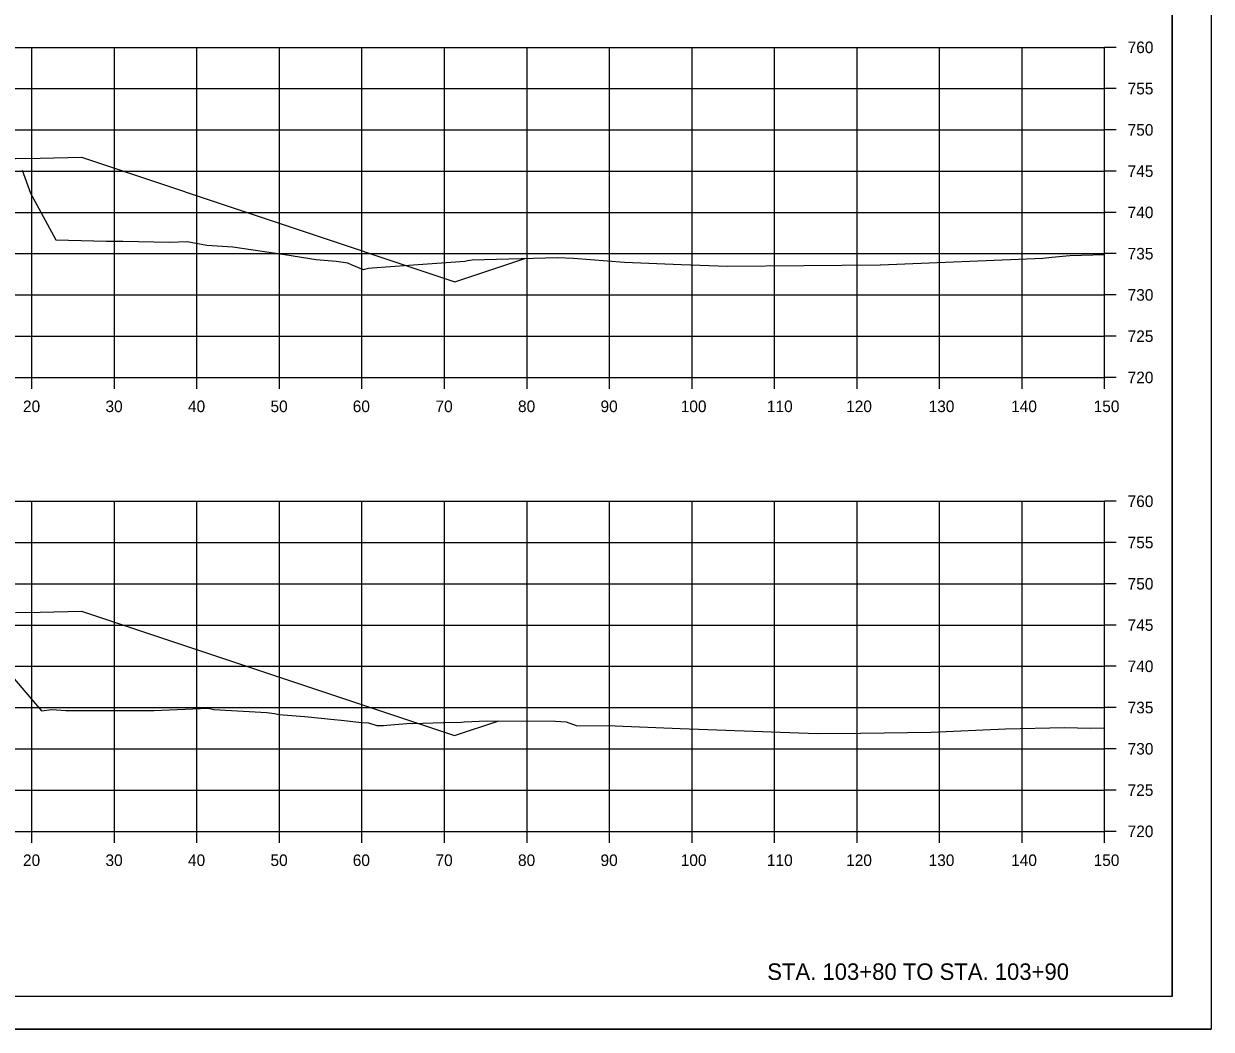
# Model space of a CAD drawing. Extents: x 1202951 to 1376887, y 378065 to 728038.
# Drawn here: x 1374304 to 1374447.9, y 379826.6 to 379948.5 of the extents above; entities that cross this region are included whole.
import ezdxf

# ---------------------------------------------------------------- set-up
doc = ezdxf.new("R2010")
doc.units = 0
for name, color, linetype in [('R_Axis', 7, 'Continuous'), ('R_Axis Annot', 7, 'Continuous'), ('R_Draft', 7, 'Continuous'), ('R_Exist Surface', 7, 'Continuous'), ('R_Fin Surface', 7, 'Continuous'), ('R_Grid', 7, 'Continuous'), ('R_No Plot', 7, 'Continuous')]:
    doc.layers.add(name, color=color, linetype=linetype)

msp = doc.modelspace()

# ---------------------------------------------------------------- linework, layer by layer
at = {"layer": 'R_Axis'}
for p, q in [((1374434.98, 379905.61), (1374434.98, 379945.61)), ((1374436.38, 379945.61), (1374434.98, 379945.61)), ((1374436.38, 379940.61), (1374434.98, 379940.61)), ((1374436.38, 379935.61), (1374434.98, 379935.61)), ((1374436.38, 379930.61), (1374434.98, 379930.61)), ((1374436.38, 379925.61), (1374434.98, 379925.61)), ((1374436.38, 379920.61), (1374434.98, 379920.61)), ((1374436.38, 379915.61), (1374434.98, 379915.61)), ((1374436.38, 379910.61), (1374434.98, 379910.61)), ((1374134.98, 379905.61), (1374434.98, 379905.61)), ((1374304.98, 379904.21), (1374304.98, 379905.61)), ((1374314.98, 379904.21), (1374314.98, 379905.61)), ((1374324.98, 379904.21), (1374324.98, 379905.61)), ((1374334.98, 379904.21), (1374334.98, 379905.61)), ((1374344.98, 379904.21), (1374344.98, 379905.61)), ((1374354.98, 379904.21), (1374354.98, 379905.61)), ((1374364.98, 379904.21), (1374364.98, 379905.61)), ((1374374.98, 379904.21), (1374374.98, 379905.61)), ((1374384.98, 379904.21), (1374384.98, 379905.61)), ((1374394.98, 379904.21), (1374394.98, 379905.61)), ((1374404.98, 379904.21), (1374404.98, 379905.61)), ((1374414.98, 379904.21), (1374414.98, 379905.61)), ((1374424.98, 379904.21), (1374424.98, 379905.61)), ((1374434.98, 379904.21), (1374434.98, 379905.61)), ((1374436.38, 379905.61), (1374434.98, 379905.61)), ((1374434.98, 379850.61), (1374434.98, 379890.61)), ((1374436.38, 379890.61), (1374434.98, 379890.61)), ((1374436.38, 379885.61), (1374434.98, 379885.61)), ((1374436.38, 379880.61), (1374434.98, 379880.61)), ((1374436.38, 379875.61), (1374434.98, 379875.61)), ((1374436.38, 379870.61), (1374434.98, 379870.61)), ((1374436.38, 379865.61), (1374434.98, 379865.61)), ((1374436.38, 379860.61), (1374434.98, 379860.61)), ((1374436.38, 379855.61), (1374434.98, 379855.61)), ((1374134.98, 379850.61), (1374434.98, 379850.61)), ((1374304.98, 379849.21), (1374304.98, 379850.61)), ((1374314.98, 379849.21), (1374314.98, 379850.61)), ((1374324.98, 379849.21), (1374324.98, 379850.61)), ((1374334.98, 379849.21), (1374334.98, 379850.61)), ((1374344.98, 379849.21), (1374344.98, 379850.61)), ((1374354.98, 379849.21), (1374354.98, 379850.61)), ((1374364.98, 379849.21), (1374364.98, 379850.61)), ((1374374.98, 379849.21), (1374374.98, 379850.61)), ((1374384.98, 379849.21), (1374384.98, 379850.61)), ((1374394.98, 379849.21), (1374394.98, 379850.61)), ((1374404.98, 379849.21), (1374404.98, 379850.61)), ((1374414.98, 379849.21), (1374414.98, 379850.61)), ((1374424.98, 379849.21), (1374424.98, 379850.61)), ((1374434.98, 379849.21), (1374434.98, 379850.61)), ((1374436.38, 379850.61), (1374434.98, 379850.61))]:
    msp.add_line(p, q, dxfattribs=at)
at = {"layer": 'R_Exist Surface'}
for points in [[(1374303.79, 379930.74), (1374304.79, 379927.92), (1374307.86, 379922.27), (1374314.03, 379922.13), (1374316, 379922.12), (1374321.64, 379922), (1374323.8, 379922.09), (1374326.19, 379921.63), (1374329.31, 379921.44), (1374335.62, 379920.52), (1374339.41, 379919.91), (1374341.87, 379919.7), (1374343, 379919.53), (1374343.23, 379919.51), (1374343.75, 379919.25), (1374345.13, 379918.7), (1374345.77, 379918.84), (1374346.2, 379918.88), (1374350.66, 379919.2), (1374357.46, 379919.7), (1374357.76, 379919.78), (1374358.35, 379919.88), (1374368.71, 379920.13), (1374370.63, 379920.08), (1374376.78, 379919.58), (1374383.67, 379919.3), (1374389.29, 379919.1), (1374407.77, 379919.24), (1374407.82, 379919.24), (1374407.83, 379919.24), (1374427.48, 379920.08), (1374428.61, 379920.19), (1374430.77, 379920.4), (1374434.98, 379920.51)], [(1374302.6, 379869.38), (1374306.13, 379865.23), (1374307.38, 379865.37), (1374309.1, 379865.26), (1374319.61, 379865.24), (1374319.65, 379865.24), (1374319.79, 379865.25), (1374326.32, 379865.52), (1374327.01, 379865.39), (1374333.45, 379865), (1374334.37, 379864.87), (1374334.92, 379864.78), (1374338.05, 379864.51), (1374341.61, 379864.17), (1374342.44, 379864.07), (1374344.95, 379863.79), (1374345.78, 379863.76), (1374346.77, 379863.44), (1374347.58, 379863.45), (1374347.99, 379863.49), (1374350.91, 379863.7), (1374351.09, 379863.67), (1374354.86, 379863.79), (1374357.04, 379863.83), (1374357.36, 379863.86), (1374360.1, 379864.02), (1374368.45, 379863.96), (1374369.73, 379863.86), (1374370.92, 379863.45), (1374375.66, 379863.38), (1374383.56, 379863.06), (1374400.14, 379862.47), (1374405.41, 379862.51), (1374413.98, 379862.61), (1374422.97, 379863.04), (1374430.14, 379863.18), (1374433.28, 379863.13), (1374434.98, 379863.16)]]:
    msp.add_lwpolyline(points, dxfattribs=at)
at = {"layer": 'R_Fin Surface'}
for points in [[(1374193.18, 379923.57), (1374196.24, 379922.56), (1374208.04, 379918.62), (1374209.01, 379919.28), (1374216.4, 379921.41), (1374229.62, 379925.81), (1374247.4, 379931.74), (1374248.44, 379932.09), (1374253.44, 379931.99), (1374256.44, 379931.93), (1374256.93, 379931.93), (1374256.94, 379931.43), (1374257.94, 379931.45), (1374284.98, 379931.99), (1374301.48, 379931.66), (1374302.48, 379931.64), (1374302.49, 379932.14), (1374302.98, 379932.14), (1374305.98, 379932.2), (1374310.98, 379932.3), (1374312.56, 379931.77), (1374356.23, 379917.21), (1374364.7, 379920.03)], [(1374302.98, 379877.12), (1374305.98, 379877.18), (1374310.98, 379877.28), (1374312.32, 379876.84), (1374356.19, 379862.21), (1374361.57, 379864.01)]]:
    msp.add_lwpolyline(points, dxfattribs=at)
at = {"layer": 'R_Grid'}
for p, q in [((1374134.98, 379945.61), (1374434.98, 379945.61)), ((1374304.98, 379905.61), (1374304.98, 379945.61)), ((1374314.98, 379905.61), (1374314.98, 379945.61)), ((1374324.98, 379905.61), (1374324.98, 379945.61)), ((1374334.98, 379905.61), (1374334.98, 379945.61)), ((1374344.98, 379905.61), (1374344.98, 379945.61)), ((1374354.98, 379905.61), (1374354.98, 379945.61)), ((1374364.98, 379905.61), (1374364.98, 379945.61)), ((1374374.98, 379905.61), (1374374.98, 379945.61)), ((1374384.98, 379905.61), (1374384.98, 379945.61)), ((1374394.98, 379905.61), (1374394.98, 379945.61)), ((1374404.98, 379905.61), (1374404.98, 379945.61)), ((1374414.98, 379905.61), (1374414.98, 379945.61)), ((1374424.98, 379905.61), (1374424.98, 379945.61)), ((1374434.98, 379905.61), (1374434.98, 379945.61)), ((1374134.98, 379940.61), (1374434.98, 379940.61)), ((1374134.98, 379935.61), (1374434.98, 379935.61)), ((1374134.98, 379930.61), (1374434.98, 379930.61)), ((1374134.98, 379925.61), (1374434.98, 379925.61)), ((1374134.98, 379920.61), (1374434.98, 379920.61)), ((1374134.98, 379915.61), (1374434.98, 379915.61)), ((1374134.98, 379910.61), (1374434.98, 379910.61)), ((1374134.98, 379905.61), (1374434.98, 379905.61)), ((1374134.98, 379890.61), (1374434.98, 379890.61)), ((1374304.98, 379850.61), (1374304.98, 379890.61)), ((1374314.98, 379850.61), (1374314.98, 379890.61)), ((1374324.98, 379850.61), (1374324.98, 379890.61)), ((1374334.98, 379850.61), (1374334.98, 379890.61)), ((1374344.98, 379850.61), (1374344.98, 379890.61)), ((1374354.98, 379850.61), (1374354.98, 379890.61)), ((1374364.98, 379850.61), (1374364.98, 379890.61)), ((1374374.98, 379850.61), (1374374.98, 379890.61)), ((1374384.98, 379850.61), (1374384.98, 379890.61)), ((1374394.98, 379850.61), (1374394.98, 379890.61)), ((1374404.98, 379850.61), (1374404.98, 379890.61)), ((1374414.98, 379850.61), (1374414.98, 379890.61)), ((1374424.98, 379850.61), (1374424.98, 379890.61)), ((1374434.98, 379850.61), (1374434.98, 379890.61)), ((1374134.98, 379885.61), (1374434.98, 379885.61)), ((1374134.98, 379880.61), (1374434.98, 379880.61)), ((1374134.98, 379875.61), (1374434.98, 379875.61)), ((1374134.98, 379870.61), (1374434.98, 379870.61)), ((1374134.98, 379865.61), (1374434.98, 379865.61)), ((1374134.98, 379860.61), (1374434.98, 379860.61)), ((1374134.98, 379855.61), (1374434.98, 379855.61)), ((1374134.98, 379850.61), (1374434.98, 379850.61))]:
    msp.add_line(p, q, dxfattribs=at)
at = {"layer": 'R_No Plot'}
for p, q in [((1374443.16, 379830.61), (1374443.16, 380036.07)), ((1374443.16, 379830.61), (1374126.98, 379830.61)), ((1374114.58, 379826.63), (1374447.91, 379826.63))]:
    msp.add_line(p, q, dxfattribs=at)
for points in [[(1374114.57, 380039.97), (1374447.91, 380039.97), (1374447.91, 379826.63), (1374114.57, 379826.63)], [(1374360.9, 380036.07), (1374380.52, 380036.07), (1374380.52, 380026.19), (1374396.63, 380026.19), (1374419.83, 380026.19), (1374419.83, 380001.86), (1374443.16, 380001.86), (1374443.16, 379830.61), (1374126.98, 379830.61), (1374126.98, 380036.07)]]:
    msp.add_lwpolyline(points, close=True, dxfattribs=at)

# ---------------------------------------------------------------- texts
at = {"layer": 'R_Axis Annot'}
for s, p in [('760', (1374437.78, 379944.91)), ('755', (1374437.78, 379939.91)), ('750', (1374437.78, 379934.91)), ('745', (1374437.78, 379929.91)), ('740', (1374437.78, 379924.91)), ('735', (1374437.78, 379919.91)), ('730', (1374437.78, 379914.91)), ('725', (1374437.78, 379909.91)), ('720', (1374437.78, 379904.91)), ('20', (1374303.89, 379901.41)), ('30', (1374313.89, 379901.41)), ('40', (1374323.89, 379901.41)), ('50', (1374333.89, 379901.41)), ('60', (1374343.86, 379901.41)), ('70', (1374353.89, 379901.41)), ('80', (1374363.89, 379901.41)), ('90', (1374373.89, 379901.41)), ('100', (1374383.61, 379901.41)), ('110', (1374394.06, 379901.41)), ('120', (1374403.66, 379901.41)), ('130', (1374413.66, 379901.41)), ('140', (1374423.66, 379901.41)), ('150', (1374433.66, 379901.41)), ('760', (1374437.78, 379889.91)), ('755', (1374437.78, 379884.91)), ('750', (1374437.78, 379879.91)), ('745', (1374437.78, 379874.91)), ('740', (1374437.78, 379869.91)), ('735', (1374437.78, 379864.91)), ('730', (1374437.78, 379859.91)), ('725', (1374437.78, 379854.91)), ('720', (1374437.78, 379849.91)), ('20', (1374303.89, 379846.41)), ('30', (1374313.89, 379846.41)), ('40', (1374323.89, 379846.41)), ('50', (1374333.89, 379846.41)), ('60', (1374343.86, 379846.41)), ('70', (1374353.89, 379846.41)), ('80', (1374363.89, 379846.41)), ('90', (1374373.89, 379846.41)), ('100', (1374383.61, 379846.41)), ('110', (1374394.06, 379846.41)), ('120', (1374403.66, 379846.41)), ('130', (1374413.66, 379846.41)), ('140', (1374423.66, 379846.41)), ('150', (1374433.66, 379846.41))]:
    msp.add_text(s, height=1.4, dxfattribs=at).set_placement(p)
at = {"layer": 'R_Draft'}
msp.add_text('STA. 103+80 TO STA. 103+90', height=2, dxfattribs=at).set_placement((1374394.1, 379832.61))

doc.saveas('drawing.dxf')
